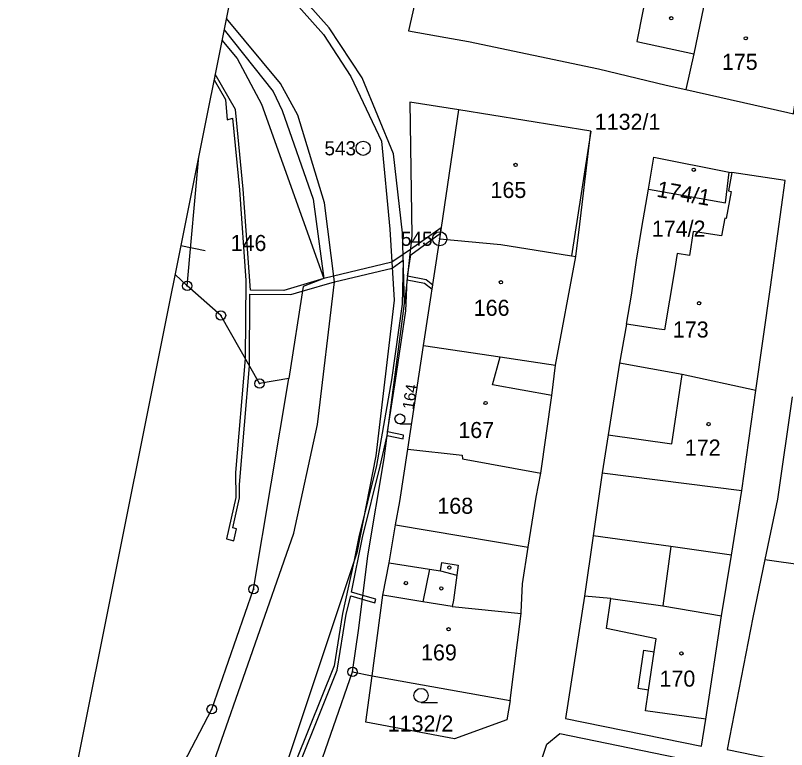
# Model space of a CAD drawing. Extents: x -548552 to -543113, y -1131925 to -1123599.
# Drawn here: x -547850.1 to -547768.4, y -1128623.7 to -1128545.9 of the extents above; entities that cross this region are included whole.
import ezdxf

# ---------------------------------------------------------------- set-up
doc = ezdxf.new("R2010")
doc.units = 0
for name, color, linetype in [('Hranice parcel', 7, 'Continuous'), ('Parcelní čísla', 7, 'Continuous'), ('Profile', 7, 'Continuous'), ('Vnitřní kresba', 7, 'Continuous'), ('Věcná břemena k části', 7, 'Continuous'), ('Značky bodu BP', 7, 'Continuous'), ('Značky budov', 7, 'Continuous'), ('Značky kultur', 7, 'Continuous')]:
    doc.layers.add(name, color=color, linetype=linetype)

msp = doc.modelspace()

# ---------------------------------------------------------------- linework, layer by layer
at = {"layer": 'Hranice parcel'}
for p, q in [((-547805.113, -1128569.551), (-547803.073, -1128555.901)), ((-547831.873, -1128574.551), (-547830.653, -1128560.836)), ((-547774.423, -1128562.491), (-547774.153, -1128562.531)), ((-547806.823, -1128580.871), (-547805.113, -1128569.551)), ((-547792.853, -1128582.951), (-547790.673, -1128571.441)), ((-547785.323, -1128578.591), (-547786.053, -1128582.751)), ((-547808.483, -1128591.841), (-547806.823, -1128580.871)), ((-547773.103, -1128596.241), (-547771.613, -1128585.651)), ((-547767.773, -1128586.321), (-547769.313, -1128597.151)), ((-547774.203, -1128603.071), (-547773.103, -1128596.241)), ((-547769.313, -1128597.151), (-547770.653, -1128603.561)), ((-547809.783, -1128599.881), (-547795.723, -1128602.251)), ((-547780.613, -1128602.181), (-547788.853, -1128601.041)), ((-547774.203, -1128603.071), (-547780.613, -1128602.181)), ((-547775.233, -1128609.511), (-547774.203, -1128603.071)), ((-547770.653, -1128603.561), (-547771.943, -1128609.691)), ((-547770.653, -1128603.561), (-547754.033, -1128605.861)), ((-547814.343, -1128615.451), (-547812.273, -1128615.861)), ((-547812.273, -1128615.861), (-547797.653, -1128618.471))]:
    msp.add_line(p, q, dxfattribs=at)
for points in [[(-547805.903, -1128536.461), (-547808.413, -1128547.531), (-547804.463, -1128548.211), (-547802.043, -1128548.651), (-547788.273, -1128551.541), (-547781.113, -1128553.271), (-547779.013, -1128553.741), (-547768.213, -1128556.181), (-547767.613, -1128556.321), (-547766.233, -1128546.981), (-547766.003, -1128545.581)], [(-547808.853, -1128576.411), (-547809.053, -1128568.941), (-547810.013, -1128560.551), (-547813.343, -1128552.511), (-547816.813, -1128547.181), (-547825.881, -1128537.031)], [(-547828.184, -1128548.518), (-547826.583, -1128550.451), (-547823.993, -1128555.281), (-547817.403, -1128573.761), (-547819.593, -1128574.601), (-547821.093, -1128584.371)], [(-547803.073, -1128555.901), (-547808.263, -1128555.091), (-547808.063, -1128569.241), (-547808.853, -1128576.411)], [(-547790.673, -1128571.441), (-547790.253, -1128568.001), (-547789.083, -1128558.141), (-547803.073, -1128555.901)], [(-547782.993, -1128564.301), (-547782.403, -1128560.911), (-547774.423, -1128562.491)], [(-547774.153, -1128562.531), (-547774.513, -1128564.481), (-547774.233, -1128564.531), (-547774.763, -1128567.391), (-547774.883, -1128567.371), (-547775.253, -1128569.231), (-547778.253, -1128568.781), (-547778.633, -1128571.331), (-547779.933, -1128571.131), (-547780.223, -1128572.931), (-547781.273, -1128579.201), (-547781.843, -1128579.151), (-547785.323, -1128578.591)], [(-547782.993, -1128564.301), (-547774.843, -1128565.731), (-547774.423, -1128562.491)], [(-547771.613, -1128585.651), (-547770.043, -1128574.691), (-547768.493, -1128563.391), (-547774.153, -1128562.531)], [(-547785.323, -1128578.591), (-547784.793, -1128575.541), (-547784.253, -1128571.811), (-547783.703, -1128568.361), (-547782.993, -1128564.301)], [(-547805.113, -1128569.551), (-547798.643, -1128570.171), (-547791.153, -1128571.361), (-547790.673, -1128571.441)], [(-547831.873, -1128574.551), (-547833.162, -1128573.356)], [(-547821.093, -1128584.371), (-547824.203, -1128584.901), (-547828.293, -1128577.681), (-547831.873, -1128574.551)], [(-547814.343, -1128615.451), (-547813.693, -1128610.821), (-547812.743, -1128603.171), (-547811.013, -1128592.841), (-547808.853, -1128576.411)], [(-547806.823, -1128580.871), (-547798.713, -1128582.081), (-547792.853, -1128582.951)], [(-547794.383, -1128594.401), (-547793.233, -1128586.171), (-547792.853, -1128582.951)], [(-547786.053, -1128582.751), (-547787.273, -1128590.341), (-547787.903, -1128594.371), (-547788.853, -1128601.041)], [(-547771.613, -1128585.651), (-547779.433, -1128583.941), (-547786.053, -1128582.751)], [(-547850.073, -1128659.301), (-547829.273, -1128619.411), (-547824.833, -1128606.691), (-547821.093, -1128584.371)], [(-547809.783, -1128599.881), (-547809.353, -1128597.391), (-547808.483, -1128591.841)], [(-547808.483, -1128591.841), (-547802.743, -1128592.471), (-547802.683, -1128592.881), (-547794.383, -1128594.401)], [(-547795.723, -1128602.251), (-547794.883, -1128596.941), (-547794.383, -1128594.401)], [(-547812.273, -1128615.861), (-547811.143, -1128607.321), (-547810.473, -1128603.881), (-547809.783, -1128599.881)], [(-547788.853, -1128601.041), (-547789.763, -1128607.441), (-547791.773, -1128620.391), (-547777.373, -1128623.341), (-547776.903, -1128620.471), (-547775.233, -1128609.511)], [(-547797.653, -1128618.471), (-547796.483, -1128609.271), (-547796.463, -1128609.141), (-547796.333, -1128606.121), (-547795.723, -1128602.251)], [(-547771.943, -1128609.691), (-547774.653, -1128623.671), (-547758.623, -1128626.971)], [(-547832.423, -1128655.211), (-547827.863, -1128646.201), (-547824.083, -1128638.951), (-547819.743, -1128630.401), (-547818.383, -1128627.051), (-547814.343, -1128615.451)], [(-547797.653, -1128618.471), (-547797.993, -1128620.521), (-547803.553, -1128622.551), (-547812.953, -1128620.791), (-547812.273, -1128615.861)], [(-547795.593, -1128631.511), (-547794.913, -1128626.611), (-547793.763, -1128623.101), (-547792.383, -1128621.971), (-547775.043, -1128625.561)]]:
    msp.add_lwpolyline(points, dxfattribs=at)
at = {"layer": 'Profile'}
for p, q in [((-547825.134, -1128533.306), (-547848.243, -1128648.589)), ((-547829.961, -1128570.819), (-547832.55, -1128570.3))]:
    msp.add_line(p, q, dxfattribs=at)
at = {"layer": 'Vnitřní kresba'}
for p, q in [((-547826.107, -1128538.158), (-547817.443, -1128547.891)), ((-547776.823, -1128543.441), (-547778.183, -1128549.941)), ((-547821.983, -1128553.081), (-547827.722, -1128546.215)), ((-547827.96, -1128547.402), (-547822.743, -1128553.951)), ((-547817.443, -1128547.891), (-547814.533, -1128552.361)), ((-547778.183, -1128549.941), (-547779.013, -1128553.741)), ((-547814.533, -1128552.361), (-547811.273, -1128559.221)), ((-547820.153, -1128556.471), (-547821.983, -1128553.081)), ((-547822.743, -1128553.951), (-547821.813, -1128555.961)), ((-547821.813, -1128555.961), (-547818.523, -1128565.371)), ((-547817.323, -1128565.741), (-547820.153, -1128556.471)), ((-547789.083, -1128558.141), (-547791.153, -1128571.361)), ((-547811.273, -1128559.221), (-547810.383, -1128568.521)), ((-547818.523, -1128565.371), (-547817.403, -1128573.761)), ((-547816.253, -1128574.111), (-547817.323, -1128565.741)), ((-547810.383, -1128568.521), (-547809.953, -1128576.071)), ((-547818.063, -1128589.231), (-547816.253, -1128574.111)), ((-547809.953, -1128576.071), (-547811.873, -1128592.571)), ((-547799.523, -1128585.031), (-547798.713, -1128582.081)), ((-547780.503, -1128591.281), (-547779.433, -1128583.941)), ((-547793.233, -1128586.171), (-547799.523, -1128585.031)), ((-547820.583, -1128600.751), (-547818.063, -1128589.231)), ((-547787.273, -1128590.341), (-547780.503, -1128591.281)), ((-547811.873, -1128592.571), (-547813.893, -1128602.821)), ((-547787.903, -1128594.371), (-547773.103, -1128596.241)), ((-547829.843, -1128627.271), (-547820.583, -1128600.751)), ((-547780.613, -1128602.181), (-547781.473, -1128608.451)), ((-547813.893, -1128602.821), (-547822.773, -1128629.461)), ((-547805.043, -1128604.741), (-547804.903, -1128603.851)), ((-547804.903, -1128603.851), (-547803.143, -1128604.131)), ((-547810.473, -1128603.881), (-547806.183, -1128604.561)), ((-547806.183, -1128604.561), (-547806.893, -1128608.021)), ((-547806.183, -1128604.561), (-547805.043, -1128604.741)), ((-547803.143, -1128604.131), (-547803.313, -1128605.221)), ((-547805.043, -1128604.741), (-547803.313, -1128605.221)), ((-547803.313, -1128605.221), (-547803.643, -1128607.871)), ((-547806.893, -1128608.021), (-547811.143, -1128607.321)), ((-547803.643, -1128607.871), (-547803.803, -1128608.521)), ((-547786.993, -1128607.691), (-547789.763, -1128607.441)), ((-547787.453, -1128610.861), (-547786.993, -1128607.691)), ((-547786.993, -1128607.691), (-547781.473, -1128608.451)), ((-547803.803, -1128608.521), (-547806.893, -1128608.021)), ((-547803.803, -1128608.521), (-547796.483, -1128609.271)), ((-547781.473, -1128608.451), (-547775.233, -1128609.511)), ((-547782.163, -1128611.941), (-547787.453, -1128610.861)), ((-547782.373, -1128613.321), (-547782.163, -1128611.941)), ((-547784.073, -1128617.211), (-547783.463, -1128613.161)), ((-547783.463, -1128613.161), (-547782.373, -1128613.321)), ((-547782.983, -1128617.381), (-547782.373, -1128613.321)), ((-547782.983, -1128617.381), (-547784.073, -1128617.211)), ((-547783.313, -1128619.581), (-547782.983, -1128617.381)), ((-547776.903, -1128620.471), (-547783.313, -1128619.581))]:
    msp.add_line(p, q, dxfattribs=at)
msp.add_lwpolyline([(-547776.823, -1128543.441), (-547782.963, -1128542.181), (-547784.233, -1128548.641), (-547778.183, -1128549.941)], dxfattribs=at)
at = {"layer": 'Věcná břemena k části'}
msp.add_line((-547828.901, -1128552.099), (-547829.025, -1128552.715), dxfattribs=at)
for points in [[(-547821.813, -1128629.811), (-547815.993, -1128615.281), (-547815.023, -1128609.341), (-547814.543, -1128607.401), (-547813.313, -1128607.751), (-547811.993, -1128608.121), (-547811.893, -1128607.741), (-547813.263, -1128607.351), (-547814.453, -1128607.011), (-547813.293, -1128601.211), (-547811.423, -1128593.661), (-547810.693, -1128590.391), (-547808.993, -1128590.761), (-547808.943, -1128590.361), (-547810.643, -1128590.001), (-547809.803, -1128584.581), (-547808.713, -1128577.201), (-547808.573, -1128573.901), (-547806.723, -1128574.271), (-547805.923, -1128574.911), (-547805.853, -1128574.461), (-547806.543, -1128573.891), (-547808.533, -1128573.501), (-547808.173, -1128571.241), (-547805.023, -1128568.961), (-547804.943, -1128568.401), (-547808.223, -1128570.681), (-547808.993, -1128571.211), (-547810.183, -1128572.041), (-547817.403, -1128573.761), (-547821.623, -1128575.041), (-547825.163, -1128575.011), (-547825.943, -1128564.311), (-547826.743, -1128555.861), (-547828.901, -1128552.099)], [(-547829.025, -1128552.715), (-547827.813, -1128554.811), (-547827.633, -1128556.931), (-547827.063, -1128556.771), (-547826.343, -1128564.351), (-547825.643, -1128573.961), (-547825.713, -1128582.241), (-547826.743, -1128594.311), (-547826.713, -1128596.981), (-547827.693, -1128601.371), (-547826.943, -1128601.551), (-547826.633, -1128600.301), (-547827.023, -1128600.201), (-547826.313, -1128597.021), (-547826.333, -1128595.601), (-547825.273, -1128583.011), (-547825.243, -1128575.411), (-547820.893, -1128575.451), (-547819.673, -1128575.091), (-547816.253, -1128574.111), (-547810.143, -1128572.671), (-547808.973, -1128571.821), (-547809.083, -1128576.481), (-547810.203, -1128584.521), (-547811.823, -1128593.581), (-547813.693, -1128601.131), (-547814.213, -1128603.781), (-547815.423, -1128609.261), (-547816.313, -1128614.811), (-547824.353, -1128634.841)]]:
    msp.add_lwpolyline(points, dxfattribs=at)
at = {"layer": 'Značky bodu BP'}
for centre, radius in [((-547813.223, -1128559.961), 0.75), ((-547813.223, -1128559.961), 0.03), ((-547805.113, -1128569.551), 0.75), ((-547805.113, -1128569.551), 0.03), ((-547831.873, -1128574.551), 0.5), ((-547831.873, -1128574.551), 0.0303), ((-547828.293, -1128577.681), 0.5), ((-547828.293, -1128577.681), 0.0303), ((-547824.203, -1128584.901), 0.5), ((-547824.203, -1128584.901), 0.0303), ((-547824.833, -1128606.691), 0.5), ((-547824.833, -1128606.691), 0.0303), ((-547814.343, -1128615.451), 0.5), ((-547814.343, -1128615.451), 0.0303), ((-547829.273, -1128619.411), 0.5), ((-547829.273, -1128619.411), 0.0303)]:
    msp.add_circle(centre, radius, dxfattribs=at)
at = {"layer": 'Značky budov'}
for centre in [(-547780.57, -1128546.18), (-547772.68, -1128548.31), (-547797.07, -1128561.72), (-547778.19, -1128562.24), (-547798.63, -1128574.16), (-547777.62, -1128576.38), (-547800.25, -1128586.96), (-547776.62, -1128589.19), (-547804.09, -1128604.4), (-547808.69, -1128606.05), (-547804.94, -1128606.61), (-547804.17, -1128610.94), (-547779.5, -1128613.5)]:
    msp.add_circle(centre, 0.175, dxfattribs=at)
at = {"layer": 'Značky kultur'}
for p, q in [((-547809.328, -1128589.171), (-547808.103, -1128589.171)), ((-547807.086, -1128618.701), (-547805.336, -1128618.701))]:
    msp.add_line(p, q, dxfattribs=at)
for centre, radius in [((-547809.328, -1128588.646), 0.525), ((-547807.086, -1128617.951), 0.75)]:
    msp.add_circle(centre, radius, dxfattribs=at)

# ---------------------------------------------------------------- texts
at = {"layer": 'Parcelní čísla'}
for s, p in [('175', (-547775.208, -1128551.651)), ('1132/1', (-547788.68, -1128558.001)), ('165', (-547799.728, -1128565.231)), ('174/2', (-547782.633, -1128569.331)), ('146', (-547827.268, -1128570.851)), ('166', (-547801.508, -1128577.721)), ('173', (-547780.408, -1128580.021)), ('167', (-547803.138, -1128590.671)), ('172', (-547779.138, -1128592.531)), ('168', (-547805.358, -1128598.701)), ('169', (-547807.088, -1128614.241)), ('170', (-547781.818, -1128617.021)), ('1132/2', (-547810.62, -1128621.781))]:
    msp.add_text(s, height=1.7, dxfattribs=at).set_placement(p)
for s, height, rotation, p in [('174/1', 1.7, 350, (-547782.199, -1128565.085)), ('164', 1.2, 81, (-547807.897, -1128587.705))]:
    msp.add_text(s, height=height, rotation=rotation, dxfattribs=at).set_placement(p)
at = {"layer": 'Značky bodu BP'}
for s, p in [('543', (-547817.326, -1128560.711)), ('545', (-547809.216, -1128570.301))]:
    msp.add_text(s, height=1.5, dxfattribs=at).set_placement(p)

doc.saveas('drawing.dxf')
